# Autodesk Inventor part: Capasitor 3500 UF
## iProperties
Company: Autodesk Inc.
Created: 2005-12
Part Number: Capasitor 3500 UF
Document SubType Name: Modeling
Designer: Autodesk Inc.
Density: 1 g/cm^3
Author: Autodesk Inc.
Title: Personal Computer
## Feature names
1. Extrusion1
2. Revolution1
3. Extrusion2
4. Extrusion3
5. Fillet1
6. Split1
